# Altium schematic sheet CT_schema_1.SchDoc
size 567 x 258 mm
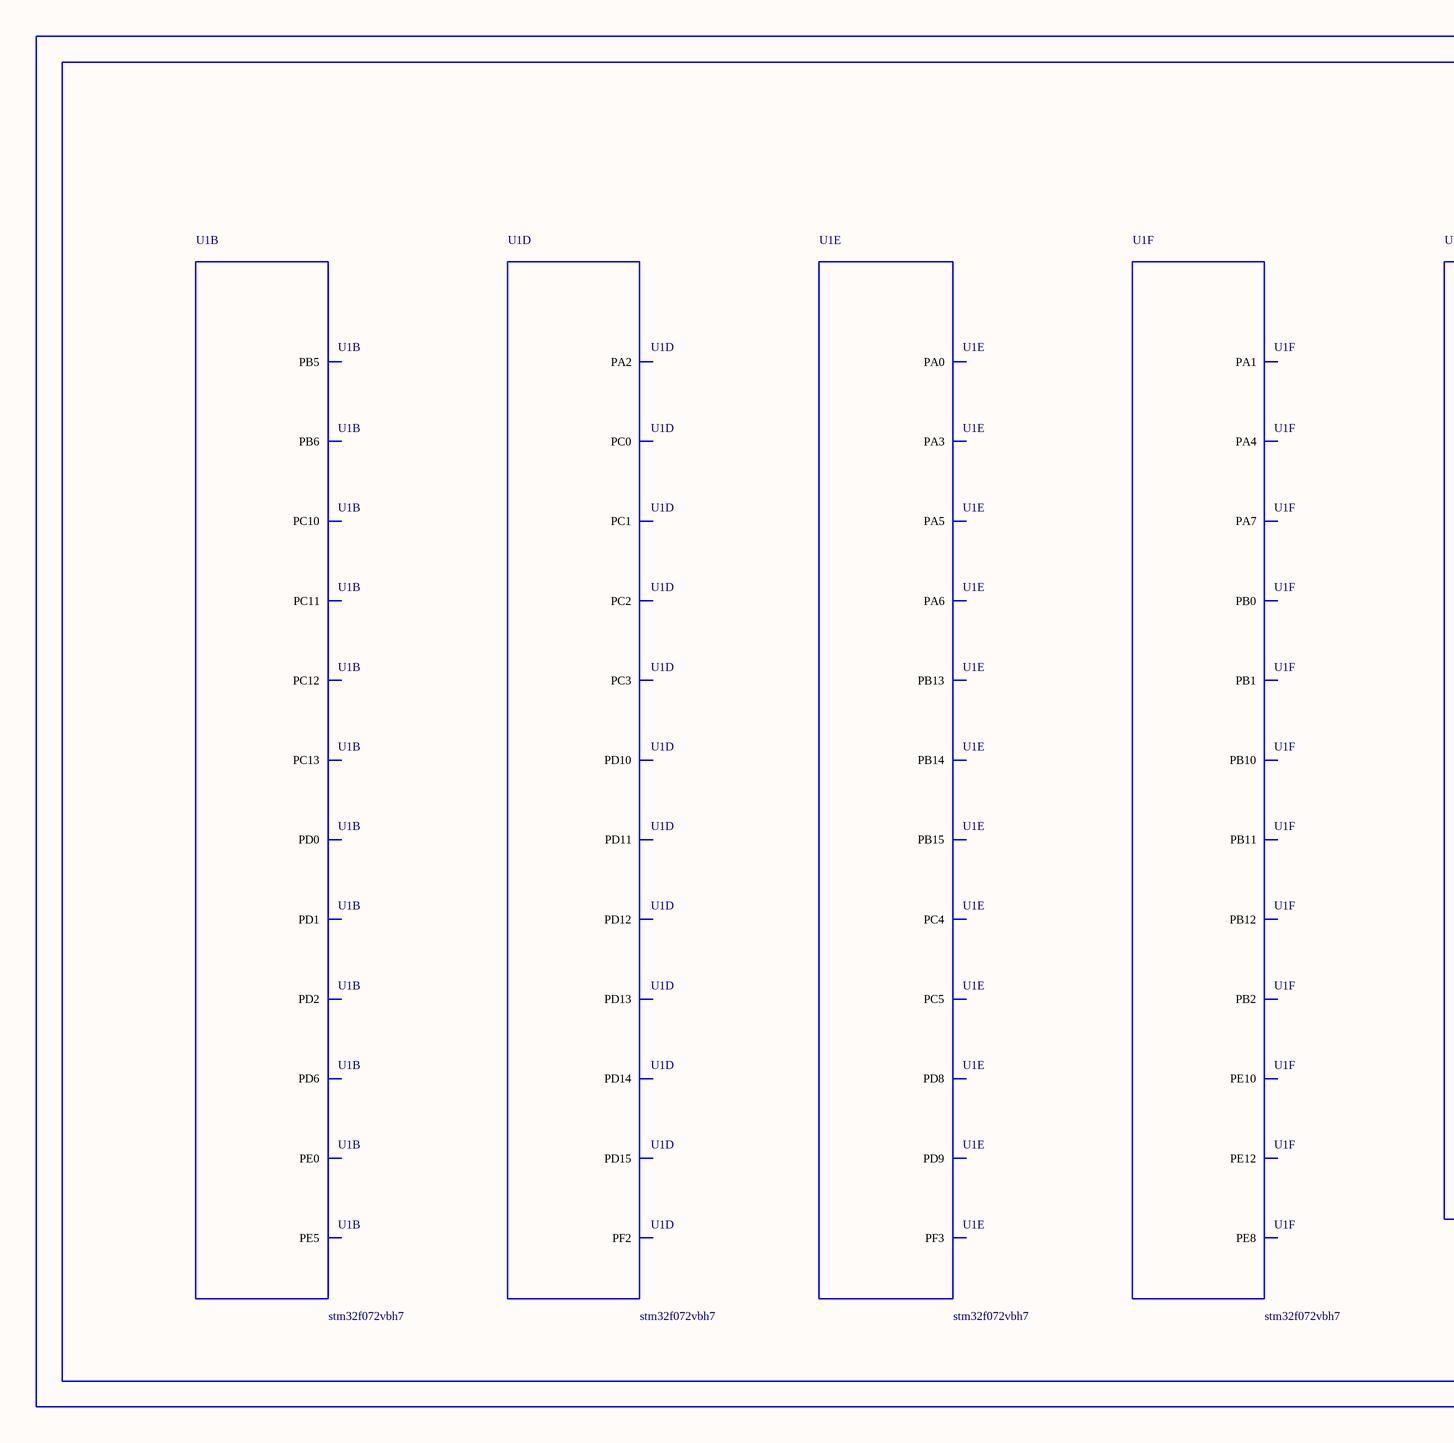
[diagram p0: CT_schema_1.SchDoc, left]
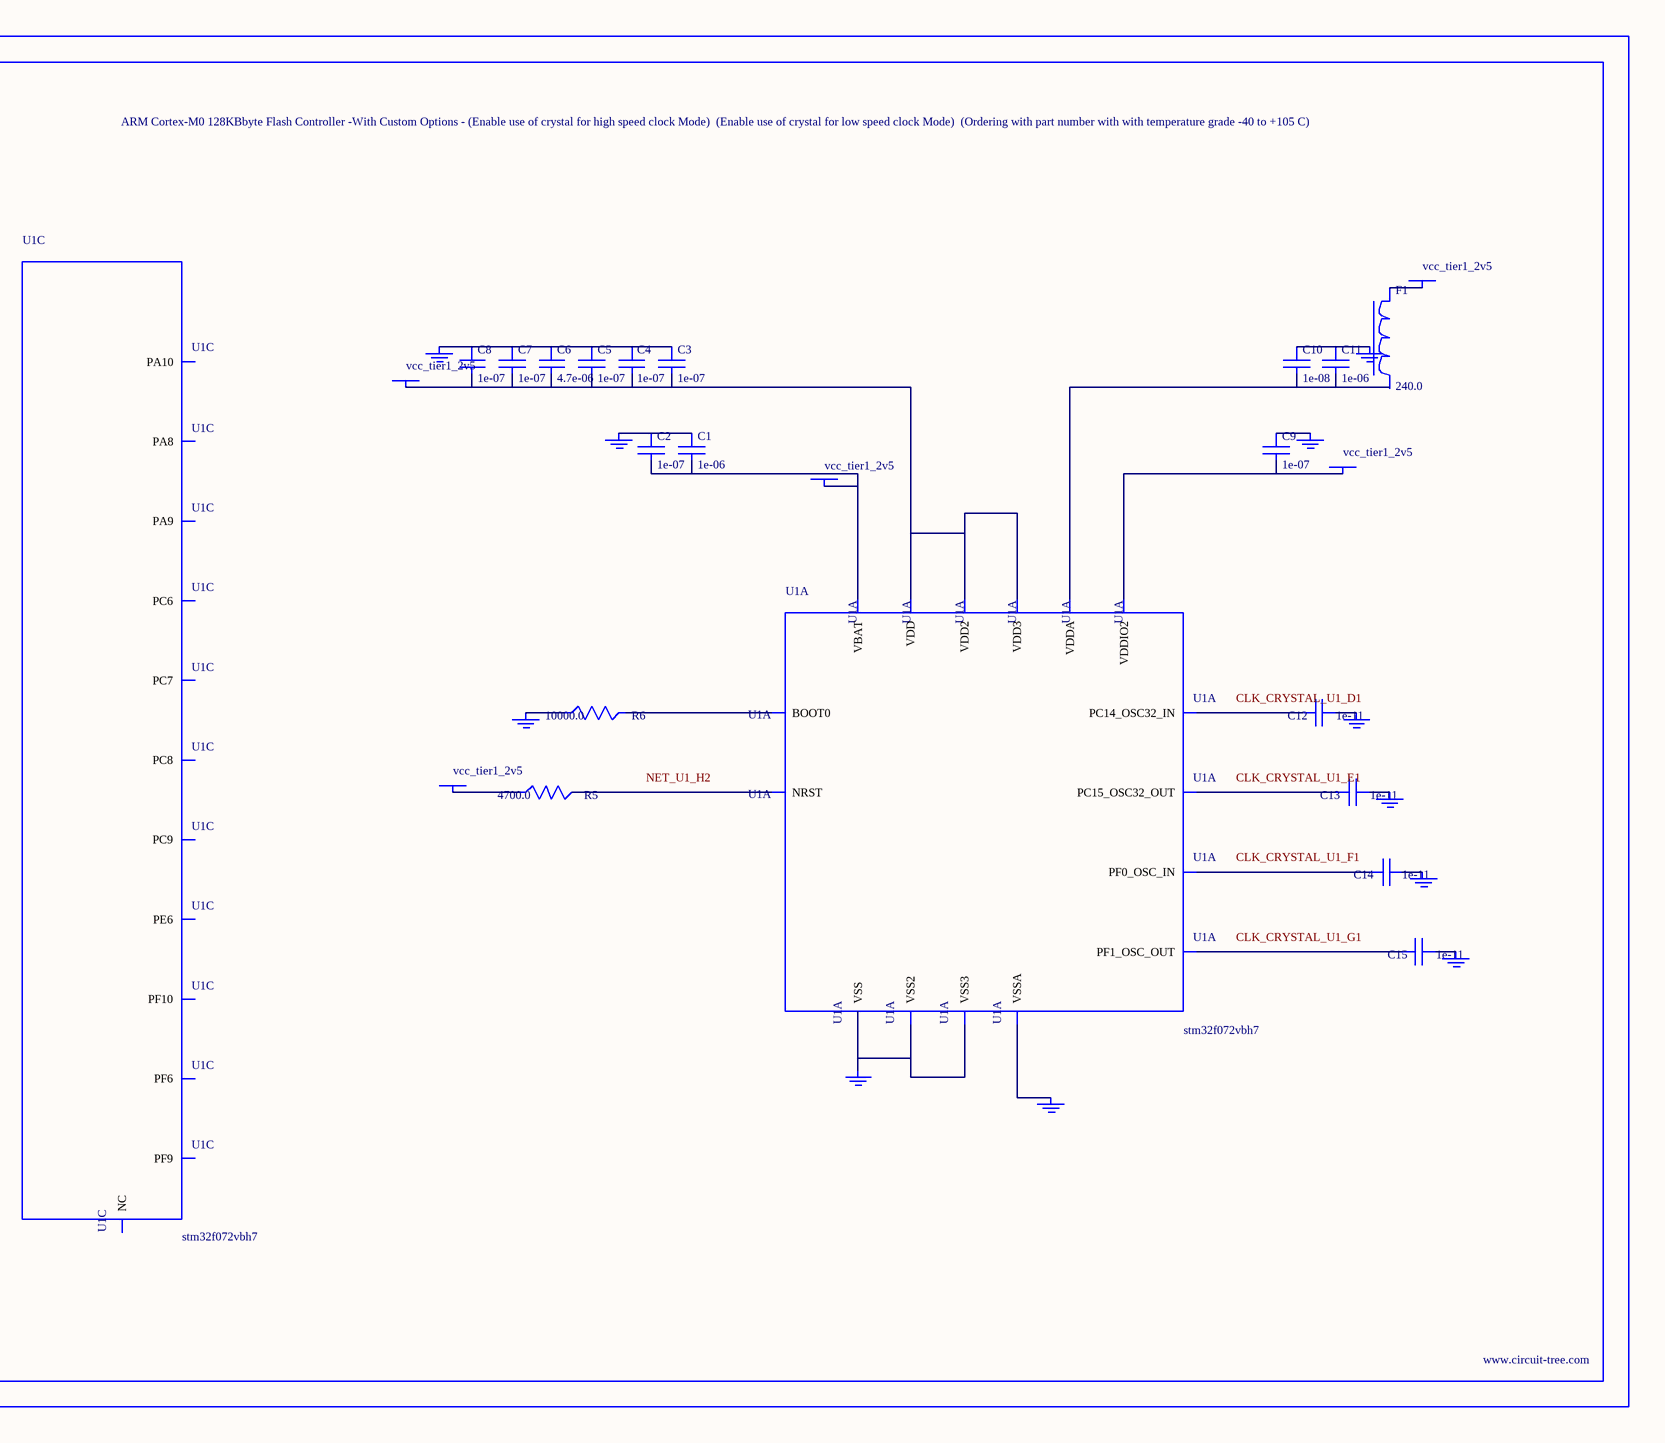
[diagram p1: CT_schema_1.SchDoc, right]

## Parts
BORDER0  (no value)
C1  1e-06  [C0603]
C2  1e-07  [C0603]
C3  1e-07  [C0603]
C4  1e-07  [C0603]
C5  1e-07  [C0603]
C6  4.7e-06  [C0603]
C7  1e-07  [C0603]
C8  1e-07  [C0603]
C9  1e-07  [C0603]
C10  1e-08  [C0603]
C11  1e-06  [C0603]
C12  1e-11  [C0402]
C13  1e-11  [C0402]
C14  1e-11  [C0402]
C15  1e-11  [C0402]
F1  240.0  [L0603]
GND_INSTANCE_0_0  (no value)
GND_INSTANCE_0_1  (no value)
GND_INSTANCE_0_2  (no value)
GND_INSTANCE_0_3  (no value)
GND_INSTANCE_0_4  (no value)
GND_INSTANCE_0_5  (no value)
GND_INSTANCE_0_6  (no value)
GND_INSTANCE_0_7  (no value)
GND_INSTANCE_0_8  (no value)
GND_INSTANCE_0_9  (no value)
GND_INSTANCE_0_10  (no value)
POWER_INSTANCE_0_0  vcc_tier1_2v5
POWER_INSTANCE_0_1  vcc_tier1_2v5
POWER_INSTANCE_0_2  vcc_tier1_2v5
POWER_INSTANCE_0_3  vcc_tier1_2v5
POWER_INSTANCE_0_4  vcc_tier1_2v5
R5  4700.0  [R0603]
R6  10000.0  [R0603]
U1  stm32f072vbh7  [UFBGA100]  (parts A,B,C,D,E,F of 9)

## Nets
NetC1_1: C1.1 C2.1 GND_INSTANCE_0_0.0(GND)
NetC1_2: C1.2 C2.2 POWER_INSTANCE_0_0.0(PWR) U1.E2(VBAT)
NetC3_1: C3.1 C4.1 C5.1 C6.1 C7.1 C8.1 GND_INSTANCE_0_2.0(GND)
NetC3_2: C3.2 C4.2 C5.2 C6.2 C7.2 C8.2 POWER_INSTANCE_0_2.0(PWR) U1.C4(VDD) U1.G12(VDD2) U1.H3(VDD3)
NetC9_1: C9.1 GND_INSTANCE_0_3.0(GND)
NetC9_2: C9.2 POWER_INSTANCE_0_3.0(PWR) U1.G11(VDDIO2)
NetC10_1: C10.1 C11.1 GND_INSTANCE_0_1.0(GND)
NetC10_2: C10.2 C11.2 U1.M1(VDDA)
NetC12_1: C12.1 GND_INSTANCE_0_5.0(GND)
NetC12_2: C12.2 U1.D1(PC14_OSC32_IN)
NetC13_1: C13.1 GND_INSTANCE_0_6.0(GND)
NetC13_2: C13.2 U1.E1(PC15_OSC32_OUT)
NetC14_1: C14.1 GND_INSTANCE_0_7.0(GND)
NetC14_2: C14.2 U1.F1(PF0_OSC_IN)
NetC15_1: C15.1 GND_INSTANCE_0_8.0(GND)
NetC15_2: C15.2 U1.G1(PF1_OSC_OUT)
NetF1_1: F1.1 POWER_INSTANCE_0_1.0(PWR)
NetGND_INSTANCE_0_4_0: GND_INSTANCE_0_4.0(GND) R6.1
NetGND_INSTANCE_0_9_0: GND_INSTANCE_0_9.0(GND) U1.K1(VSSA)
NetGND_INSTANCE_0_10_0: GND_INSTANCE_0_10.0(GND) U1.D3(VSS) U1.F11(VSS2) U1.F12(VSS3)
NetPOWER_INSTANCE_0_4_0: POWER_INSTANCE_0_4.0(PWR) R5.1
NetR5_2: R5.2 U1.H2(NRST)
NetR6_2: R6.2 U1.A4(BOOT0)

Not connected (* = marked no-connect by the designer): F1 2; U1 B5(PB6) B6(PD6) B9(PD1) B10(PC12) B11(PC10) C1(PC13) C2(PE5) C3(PE0) C5(PB5) C8(PD2) C9(PD0) C10(PC11) C11(PF6) C12(PA10) D2(PE6) D10(PA9) D11(PA8) D12(PC9) E3(NC) E10(PC8) E11(PC7) E12(PC6) F2(PF9) G2(PF10) H1(PC0) H10(PD15) H11(PD14) H12(PD13) J1(PF2) J2(PC1) J3(PC2) J10(PD12) J11(PD11) J12(PD10) K2(PC3) K3(PA2) K4(PA5) K5(PC4) K8(PD9) K9(PD8) K10(PB15) K11(PB14) K12(PB13) L1(PF3) L2(PA0) L3(PA3) L4(PA6) L5(PC5) L6(PB2) L7(PE8) L8(PE10) L9(PE12) L10(PB10) L11(PB11) L12(PB12) M2(PA1) M3(PA4) M4(PA7) M5(PB0) M6(PB1)

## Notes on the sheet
- Labels drawn without touching a wire or pin: CLK_CRYSTAL_U1_D1, CLK_CRYSTAL_U1_E1, CLK_CRYSTAL_U1_F1, CLK_CRYSTAL_U1_G1, NET_U1_H2

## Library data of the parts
BORDER0 = BORDER_PAGE0
C1 C11 = C0603C105K3RACTU
C2-C5 C7-C9 = 06035C104K4Z2A
C6 = GRM188R6YA475KE15D
C10 = 06035C103K4Z2A
C12-C15 = C0402C100K3GACTU
F1 = Z0603C241ASMST
GND_INSTANCE_0_0-GND_INSTANCE_0_10 = GND
POWER_INSTANCE_0_0-POWER_INSTANCE_0_4 = PWR
R5 = RC0603JR-074K7L
R6 = RC0603JR-0710KL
